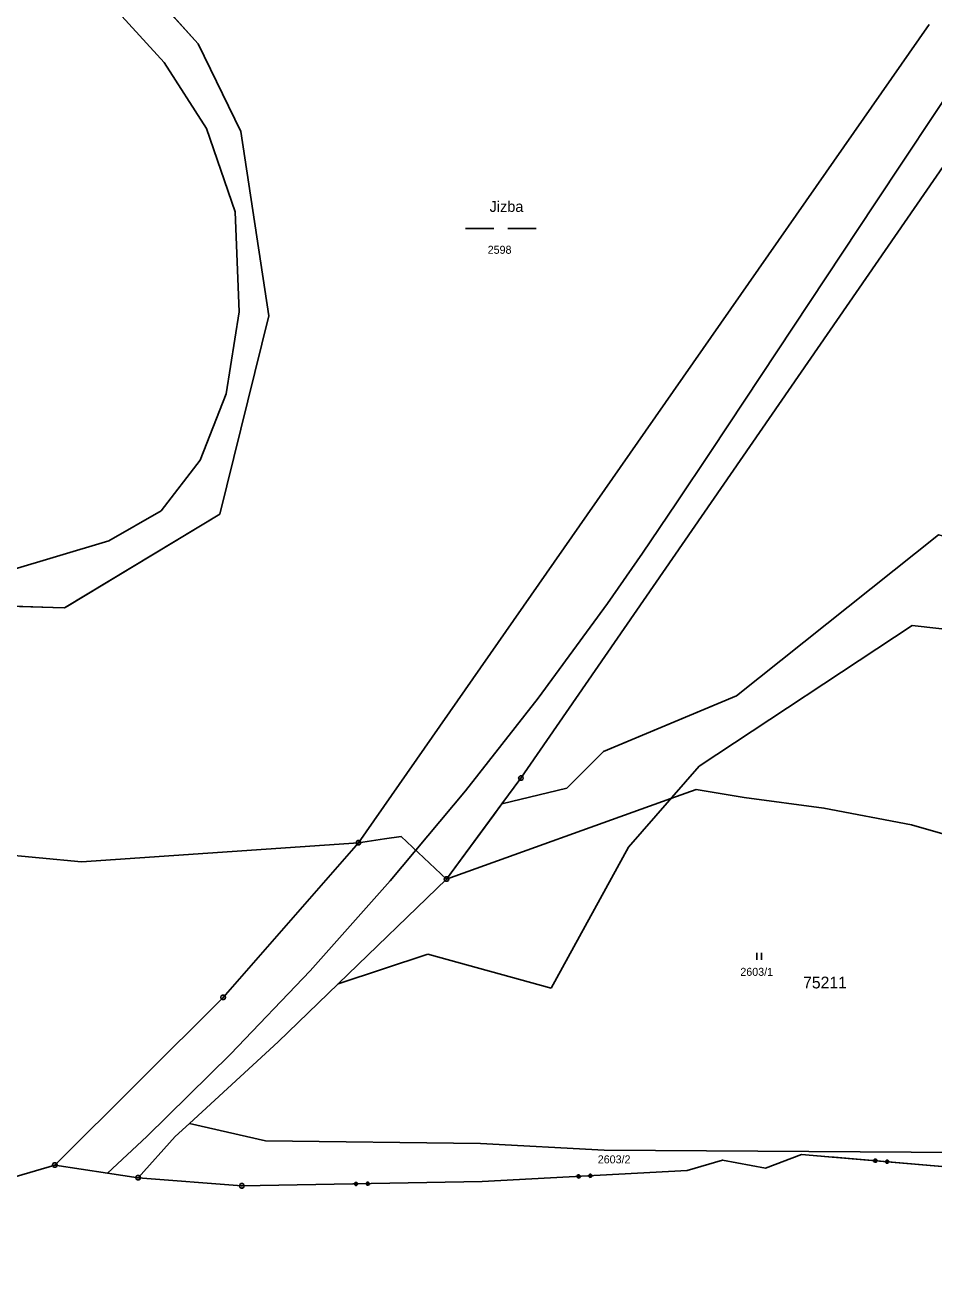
# Model space of a CAD drawing. Extents: x -760611 to -758411, y -1176479 to -1174807.
# Drawn here: x -759864.3 to -759671.2, y -1176380 to -1176113.5 of the extents above; entities that cross this region are included whole.
import ezdxf

# ---------------------------------------------------------------- set-up
doc = ezdxf.new("R2010")
doc.units = 0
for name, color, linetype in [('1', 7, 'Continuous'), ('11', 7, 'Continuous'), ('2', 7, 'Continuous'), ('3', 7, 'Continuous'), ('6', 7, 'Continuous'), ('7', 7, 'Continuous'), ('8', 7, 'Continuous')]:
    doc.layers.add(name, color=color, linetype=linetype)

msp = doc.modelspace()

# ---------------------------------------------------------------- linework, layer by layer
at = {"layer": '1'}
for p, q in [((-759860.54, -1176081.1), (-759827.51, -1176117.48)), ((-759834.72, -1176121.49), (-759850.72, -1176103.96)), ((-759672.16, -1176113.37), (-759732.47, -1176199.81)), ((-759827.51, -1176117.48), (-759818.47, -1176136.11)), ((-759825.75, -1176135.49), (-759834.72, -1176121.49)), ((-759758.92, -1176273.47), (-759655.18, -1176123.17)), ((-759819.63, -1176153.18), (-759825.75, -1176135.49)), ((-759818.47, -1176136.11), (-759812.5, -1176175.28)), ((-759818.81, -1176174.41), (-759819.63, -1176153.18)), ((-759821.57, -1176191.88), (-759818.81, -1176174.41)), ((-759812.5, -1176175.28), (-759822.93, -1176217.38)), ((-759827.11, -1176205.96), (-759821.57, -1176191.88)), ((-759793.45, -1176287.21), (-759732.47, -1176199.81)), ((-759835.37, -1176216.72), (-759827.11, -1176205.96)), ((-759822.93, -1176217.38), (-759855.89, -1176237.32)), ((-759846.49, -1176223.08), (-759835.37, -1176216.72)), ((-759868.02, -1176229.52), (-759846.49, -1176223.08)), ((-759713.13, -1176256), (-759670.2, -1176221.81)), ((-759855.89, -1176237.32), (-759943.02, -1176234.41)), ((-759675.78, -1176241.05), (-759721.04, -1176270.9)), ((-759645.11, -1176244.62), (-759675.78, -1176241.05)), ((-759741.37, -1176267.82), (-759713.13, -1176256)), ((-759749.18, -1176275.62), (-759741.37, -1176267.82)), ((-759721.04, -1176270.9), (-759736.07, -1176288.16)), ((-759763.01, -1176278.96), (-759758.92, -1176273.47)), ((-759763.01, -1176278.96), (-759749.18, -1176275.62)), ((-759774.73, -1176294.92), (-759763.01, -1176278.96)), ((-759852.32, -1176291.22), (-759911.83, -1176285.7)), ((-759793.45, -1176287.21), (-759852.32, -1176291.22)), ((-759793.45, -1176287.21), (-759822.2, -1176320.03)), ((-759736.07, -1176288.16), (-759752.5, -1176318.11)), ((-759774.73, -1176294.92), (-759797.74, -1176317.15)), ((-759778.68, -1176310.83), (-759797.74, -1176317.15)), ((-759752.5, -1176318.11), (-759778.68, -1176310.83)), ((-759810.52, -1176329.5), (-759797.74, -1176317.15)), ((-759822.2, -1176320.03), (-759857.97, -1176355.65)), ((-759810.52, -1176329.5), (-759829.36, -1176346.81)), ((-759832.4, -1176349.6), (-759829.36, -1176346.81)), ((-759829.36, -1176346.81), (-759813.21, -1176350.48)), ((-759840.25, -1176358.34), (-759832.4, -1176349.6)), ((-759813.21, -1176350.48), (-759767.54, -1176351.09)), ((-759767.54, -1176351.09), (-759741.25, -1176352.48)), ((-759741.25, -1176352.48), (-759664.68, -1176352.98)), ((-759699.3, -1176353.38), (-759706.96, -1176356.34)), ((-759665.33, -1176356.29), (-759699.3, -1176353.38)), ((-759857.97, -1176355.65), (-759883.65, -1176363.22)), ((-759846.78, -1176357.35), (-759857.97, -1176355.65)), ((-759716.07, -1176354.6), (-759723.58, -1176356.83)), ((-759706.96, -1176356.34), (-759716.07, -1176354.6)), ((-759840.25, -1176358.34), (-759846.78, -1176357.35)), ((-759818.22, -1176360.08), (-759840.25, -1176358.34)), ((-759723.58, -1176356.83), (-759767.15, -1176359.17)), ((-759767.15, -1176359.17), (-759818.22, -1176360.08))]:
    msp.add_line(p, q, dxfattribs=at)
for points in [[(-759683.77, -1176355.03), (-759683.94, -1176354.83), (-759683.92, -1176354.56), (-759683.71, -1176354.38), (-759683.44, -1176354.41), (-759683.27, -1176354.61), (-759683.29, -1176354.88), (-759683.5, -1176355.05), (-759683.77, -1176355.03), (-759683.73, -1176354.99), (-759683.49, -1176355.01), (-759683.41, -1176354.94), (-759683.81, -1176354.91), (-759683.88, -1176354.82), (-759683.32, -1176354.87), (-759683.31, -1176354.79), (-759683.87, -1176354.74), (-759683.87, -1176354.66), (-759683.31, -1176354.71), (-759683.3, -1176354.63), (-759683.86, -1176354.58), (-759683.77, -1176354.51), (-759683.37, -1176354.54), (-759683.45, -1176354.46), (-759683.69, -1176354.44)], [(-759681.28, -1176355.25), (-759681.45, -1176355.04), (-759681.43, -1176354.77), (-759681.22, -1176354.6), (-759680.95, -1176354.62), (-759680.78, -1176354.83), (-759680.8, -1176355.1), (-759681.01, -1176355.27), (-759681.28, -1176355.25), (-759681.26, -1176355.21), (-759681.02, -1176355.23), (-759680.94, -1176355.15), (-759681.34, -1176355.12), (-759681.41, -1176355.03), (-759680.85, -1176355.08), (-759680.84, -1176355), (-759681.4, -1176354.95), (-759681.39, -1176354.87), (-759680.84, -1176354.92), (-759680.83, -1176354.84), (-759681.39, -1176354.79), (-759681.3, -1176354.72), (-759680.9, -1176354.76), (-759680.98, -1176354.67), (-759681.22, -1176354.65)], [(-759746.78, -1176358.4), (-759746.98, -1176358.22), (-759746.99, -1176357.95), (-759746.81, -1176357.75), (-759746.54, -1176357.73), (-759746.34, -1176357.91), (-759746.33, -1176358.18), (-759746.51, -1176358.38), (-759746.78, -1176358.4), (-759746.75, -1176358.35), (-759746.51, -1176358.34), (-759746.43, -1176358.26), (-759746.83, -1176358.28), (-759746.92, -1176358.2), (-759746.36, -1176358.17), (-759746.36, -1176358.09), (-759746.92, -1176358.12), (-759746.92, -1176358.04), (-759746.37, -1176358.01), (-759746.37, -1176357.93), (-759746.93, -1176357.96), (-759746.85, -1176357.88), (-759746.45, -1176357.86), (-759746.54, -1176357.78), (-759746.78, -1176357.8)], [(-759744.28, -1176358.26), (-759744.48, -1176358.08), (-759744.49, -1176357.81), (-759744.31, -1176357.61), (-759744.04, -1176357.6), (-759743.84, -1176357.78), (-759743.83, -1176358.05), (-759744.01, -1176358.25), (-759744.28, -1176358.26), (-759744.27, -1176358.22), (-759744.03, -1176358.21), (-759743.96, -1176358.12), (-759744.36, -1176358.15), (-759744.44, -1176358.07), (-759743.88, -1176358.04), (-759743.88, -1176357.96), (-759744.44, -1176357.99), (-759744.45, -1176357.91), (-759743.89, -1176357.88), (-759743.89, -1176357.8), (-759744.45, -1176357.83), (-759744.38, -1176357.75), (-759743.98, -1176357.73), (-759744.06, -1176357.65), (-759744.3, -1176357.66)], [(-759794.11, -1176359.97), (-759794.3, -1176359.78), (-759794.31, -1176359.51), (-759794.12, -1176359.32), (-759793.85, -1176359.32), (-759793.66, -1176359.5), (-759793.65, -1176359.77), (-759793.84, -1176359.97), (-759794.11, -1176359.97), (-759794.08, -1176359.93), (-759793.84, -1176359.93), (-759793.76, -1176359.84), (-759794.16, -1176359.85), (-759794.24, -1176359.77), (-759793.68, -1176359.76), (-759793.68, -1176359.68), (-759794.24, -1176359.69), (-759794.25, -1176359.61), (-759793.69, -1176359.6), (-759793.69, -1176359.52), (-759794.25, -1176359.53), (-759794.17, -1176359.45), (-759793.77, -1176359.44), (-759793.85, -1176359.37), (-759794.09, -1176359.37)], [(-759791.61, -1176359.93), (-759791.8, -1176359.74), (-759791.81, -1176359.47), (-759791.62, -1176359.28), (-759791.35, -1176359.27), (-759791.16, -1176359.46), (-759791.15, -1176359.73), (-759791.34, -1176359.92), (-759791.61, -1176359.93), (-759791.6, -1176359.89), (-759791.36, -1176359.88), (-759791.28, -1176359.8), (-759791.68, -1176359.81), (-759791.76, -1176359.73), (-759791.2, -1176359.72), (-759791.2, -1176359.64), (-759791.76, -1176359.65), (-759791.77, -1176359.57), (-759791.21, -1176359.56), (-759791.21, -1176359.48), (-759791.77, -1176359.49), (-759791.69, -1176359.41), (-759791.29, -1176359.4), (-759791.37, -1176359.32), (-759791.61, -1176359.33)]]:
    msp.add_lwpolyline(points, dxfattribs=at)
at = {"layer": '11'}
for points in [[(-759943.27, -1176238.32), (-759943.02, -1176234.41), (-759858.39, -1176237.24), (-759855.89, -1176237.32), (-759855.25, -1176236.93), (-759822.93, -1176217.38), (-759812.5, -1176175.28), (-759818.47, -1176136.11), (-759827.51, -1176117.48), (-759832.59, -1176111.88)], [(-759606.04, -1176195.29), (-759612.34, -1176203.66), (-759617.4, -1176212.11), (-759621.45, -1176213.36), (-759654.29, -1176223.51), (-759658.47, -1176224.8), (-759670.2, -1176221.81), (-759713.13, -1176256), (-759717.87, -1176257.99), (-759741.37, -1176267.82), (-759749.18, -1176275.62), (-759763.01, -1176278.96), (-759764.62, -1176281.16), (-759774.73, -1176294.92)], [(-759774.73, -1176294.92), (-759727.06, -1176277.81), (-759721.71, -1176275.89), (-759711.47, -1176277.57), (-759694.54, -1176279.84), (-759675.93, -1176283.39)], [(-759675.93, -1176283.39), (-759633.23, -1176295.61), (-759628.79, -1176297.1), (-759621.82, -1176299.45), (-759612.52, -1176302.57), (-759588.02, -1176312.1), (-759585.06, -1176313.81), (-759577.03, -1176316.42), (-759558.06, -1176328.86), (-759546.27, -1176339.13), (-759539.55, -1176347.65), (-759530.18, -1176365.32)], [(-759774.73, -1176294.92), (-759784.39, -1176285.83), (-759787.92, -1176286.37), (-759793.45, -1176287.21), (-759822.2, -1176320.03), (-759857.97, -1176355.65)], [(-759559.37, -1176380.04), (-759566.45, -1176373.85), (-759570.48, -1176374.72), (-759576.08, -1176369.6), (-759593.33, -1176366.03), (-759609.98, -1176364.93), (-759630.95, -1176366), (-759644.84, -1176357.58), (-759650.18, -1176357.34), (-759654.08, -1176356.99), (-759660.63, -1176356.21), (-759665.33, -1176356.29), (-759692.34, -1176353.98), (-759692.79, -1176353.94), (-759699.3, -1176353.38), (-759706.96, -1176356.34), (-759716.07, -1176354.6), (-759723.58, -1176356.83), (-759767.15, -1176359.17), (-759818.22, -1176360.08), (-759840.25, -1176358.34), (-759846.78, -1176357.35), (-759857.97, -1176355.65)]]:
    msp.add_lwpolyline(points, dxfattribs=at)
at = {"layer": '3'}
for p, q in [((-759770.71, -1176156.7), (-759764.71, -1176156.7)), ((-759761.71, -1176156.7), (-759755.71, -1176156.7)), ((-759708.78, -1176310.54), (-759708.78, -1176312.04)), ((-759707.78, -1176312.04), (-759707.78, -1176310.54))]:
    msp.add_line(p, q, dxfattribs=at)
at = {"layer": '6'}
for p, q in [((-759656.22, -1176109.98), (-759683.74, -1176151.52)), ((-759683.74, -1176151.52), (-759711.33, -1176193.2)), ((-759711.33, -1176193.2), (-759718.55, -1176204.09)), ((-759718.55, -1176204.09), (-759725.85, -1176215.01)), ((-759725.85, -1176215.01), (-759733.1, -1176225.68)), ((-759733.1, -1176225.68), (-759740.53, -1176236.35)), ((-759740.53, -1176236.35), (-759755.26, -1176256.46)), ((-759755.26, -1176256.46), (-759770.7, -1176276.18)), ((-759770.7, -1176276.18), (-759786.69, -1176295.29)), ((-759786.69, -1176295.29), (-759803.73, -1176314.37)), ((-759803.73, -1176314.37), (-759820.63, -1176332.1)), ((-759820.63, -1176332.1), (-759838.4, -1176349.61)), ((-759838.4, -1176349.61), (-759846.78, -1176357.35))]:
    msp.add_line(p, q, dxfattribs=at)
at = {"layer": '8'}
for p, q in [((-759759.04, -1176273.47), (-759758.8, -1176273.47)), ((-759793.57, -1176287.21), (-759793.33, -1176287.21)), ((-759774.85, -1176294.92), (-759774.61, -1176294.92)), ((-759822.32, -1176320.03), (-759822.08, -1176320.03)), ((-759858.09, -1176355.65), (-759857.85, -1176355.65)), ((-759840.37, -1176358.34), (-759840.13, -1176358.34)), ((-759818.34, -1176360.08), (-759818.1, -1176360.08))]:
    msp.add_line(p, q, dxfattribs=at)
for points in [[(-759758.77, -1176272.99), (-759758.52, -1176273.17), (-759758.42, -1176273.46), (-759758.52, -1176273.75), (-759758.77, -1176273.93), (-759759.08, -1176273.93), (-759759.33, -1176273.75), (-759759.43, -1176273.46), (-759759.33, -1176273.17), (-759759.08, -1176272.99)], [(-759793.3, -1176286.73), (-759793.05, -1176286.91), (-759792.95, -1176287.2), (-759793.05, -1176287.49), (-759793.3, -1176287.67), (-759793.61, -1176287.67), (-759793.86, -1176287.49), (-759793.96, -1176287.2), (-759793.86, -1176286.91), (-759793.61, -1176286.73)], [(-759774.58, -1176294.44), (-759774.33, -1176294.62), (-759774.23, -1176294.91), (-759774.33, -1176295.2), (-759774.58, -1176295.38), (-759774.89, -1176295.38), (-759775.14, -1176295.2), (-759775.24, -1176294.91), (-759775.14, -1176294.62), (-759774.89, -1176294.44)], [(-759822.05, -1176319.55), (-759821.8, -1176319.73), (-759821.7, -1176320.02), (-759821.8, -1176320.31), (-759822.05, -1176320.49), (-759822.36, -1176320.49), (-759822.61, -1176320.31), (-759822.71, -1176320.02), (-759822.61, -1176319.73), (-759822.36, -1176319.55)], [(-759857.82, -1176355.17), (-759857.57, -1176355.35), (-759857.47, -1176355.64), (-759857.57, -1176355.93), (-759857.82, -1176356.11), (-759858.13, -1176356.11), (-759858.38, -1176355.93), (-759858.48, -1176355.64), (-759858.38, -1176355.35), (-759858.13, -1176355.17)], [(-759840.1, -1176357.86), (-759839.85, -1176358.04), (-759839.75, -1176358.33), (-759839.85, -1176358.62), (-759840.1, -1176358.8), (-759840.41, -1176358.8), (-759840.66, -1176358.62), (-759840.76, -1176358.33), (-759840.66, -1176358.04), (-759840.41, -1176357.86)], [(-759818.07, -1176359.6), (-759817.82, -1176359.78), (-759817.72, -1176360.07), (-759817.82, -1176360.36), (-759818.07, -1176360.54), (-759818.38, -1176360.54), (-759818.63, -1176360.36), (-759818.73, -1176360.07), (-759818.63, -1176359.78), (-759818.38, -1176359.6)]]:
    msp.add_lwpolyline(points, close=True, dxfattribs=at)

# ---------------------------------------------------------------- texts
at = {"layer": '11'}
msp.add_text('75211', height=2.5, dxfattribs=at).set_placement((-759698.97, -1176318.13))
at = {"layer": '2'}
for s, p in [('2598', (-759765.99, -1176162.1)), ('2603/1', (-759712.31, -1176315.46)), ('2603/2', (-759742.6, -1176355.29))]:
    msp.add_text(s, height=1.7, dxfattribs=at).set_placement(p)
at = {"layer": '7'}
msp.add_text('Jizba', height=2.3, dxfattribs=at).set_placement((-759765.59, -1176153.21))

doc.saveas('drawing.dxf')
